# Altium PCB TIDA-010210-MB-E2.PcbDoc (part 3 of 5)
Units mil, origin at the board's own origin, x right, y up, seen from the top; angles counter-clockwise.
Board outline 11811.02 x 8661.42 mil, 4 copper layers (Top Layer, Gnd Layer, Pwr Layer, Bottom Layer), stack 94.4 mil thick; 473 components, 257 nets, 1291 pads, 289 vias.
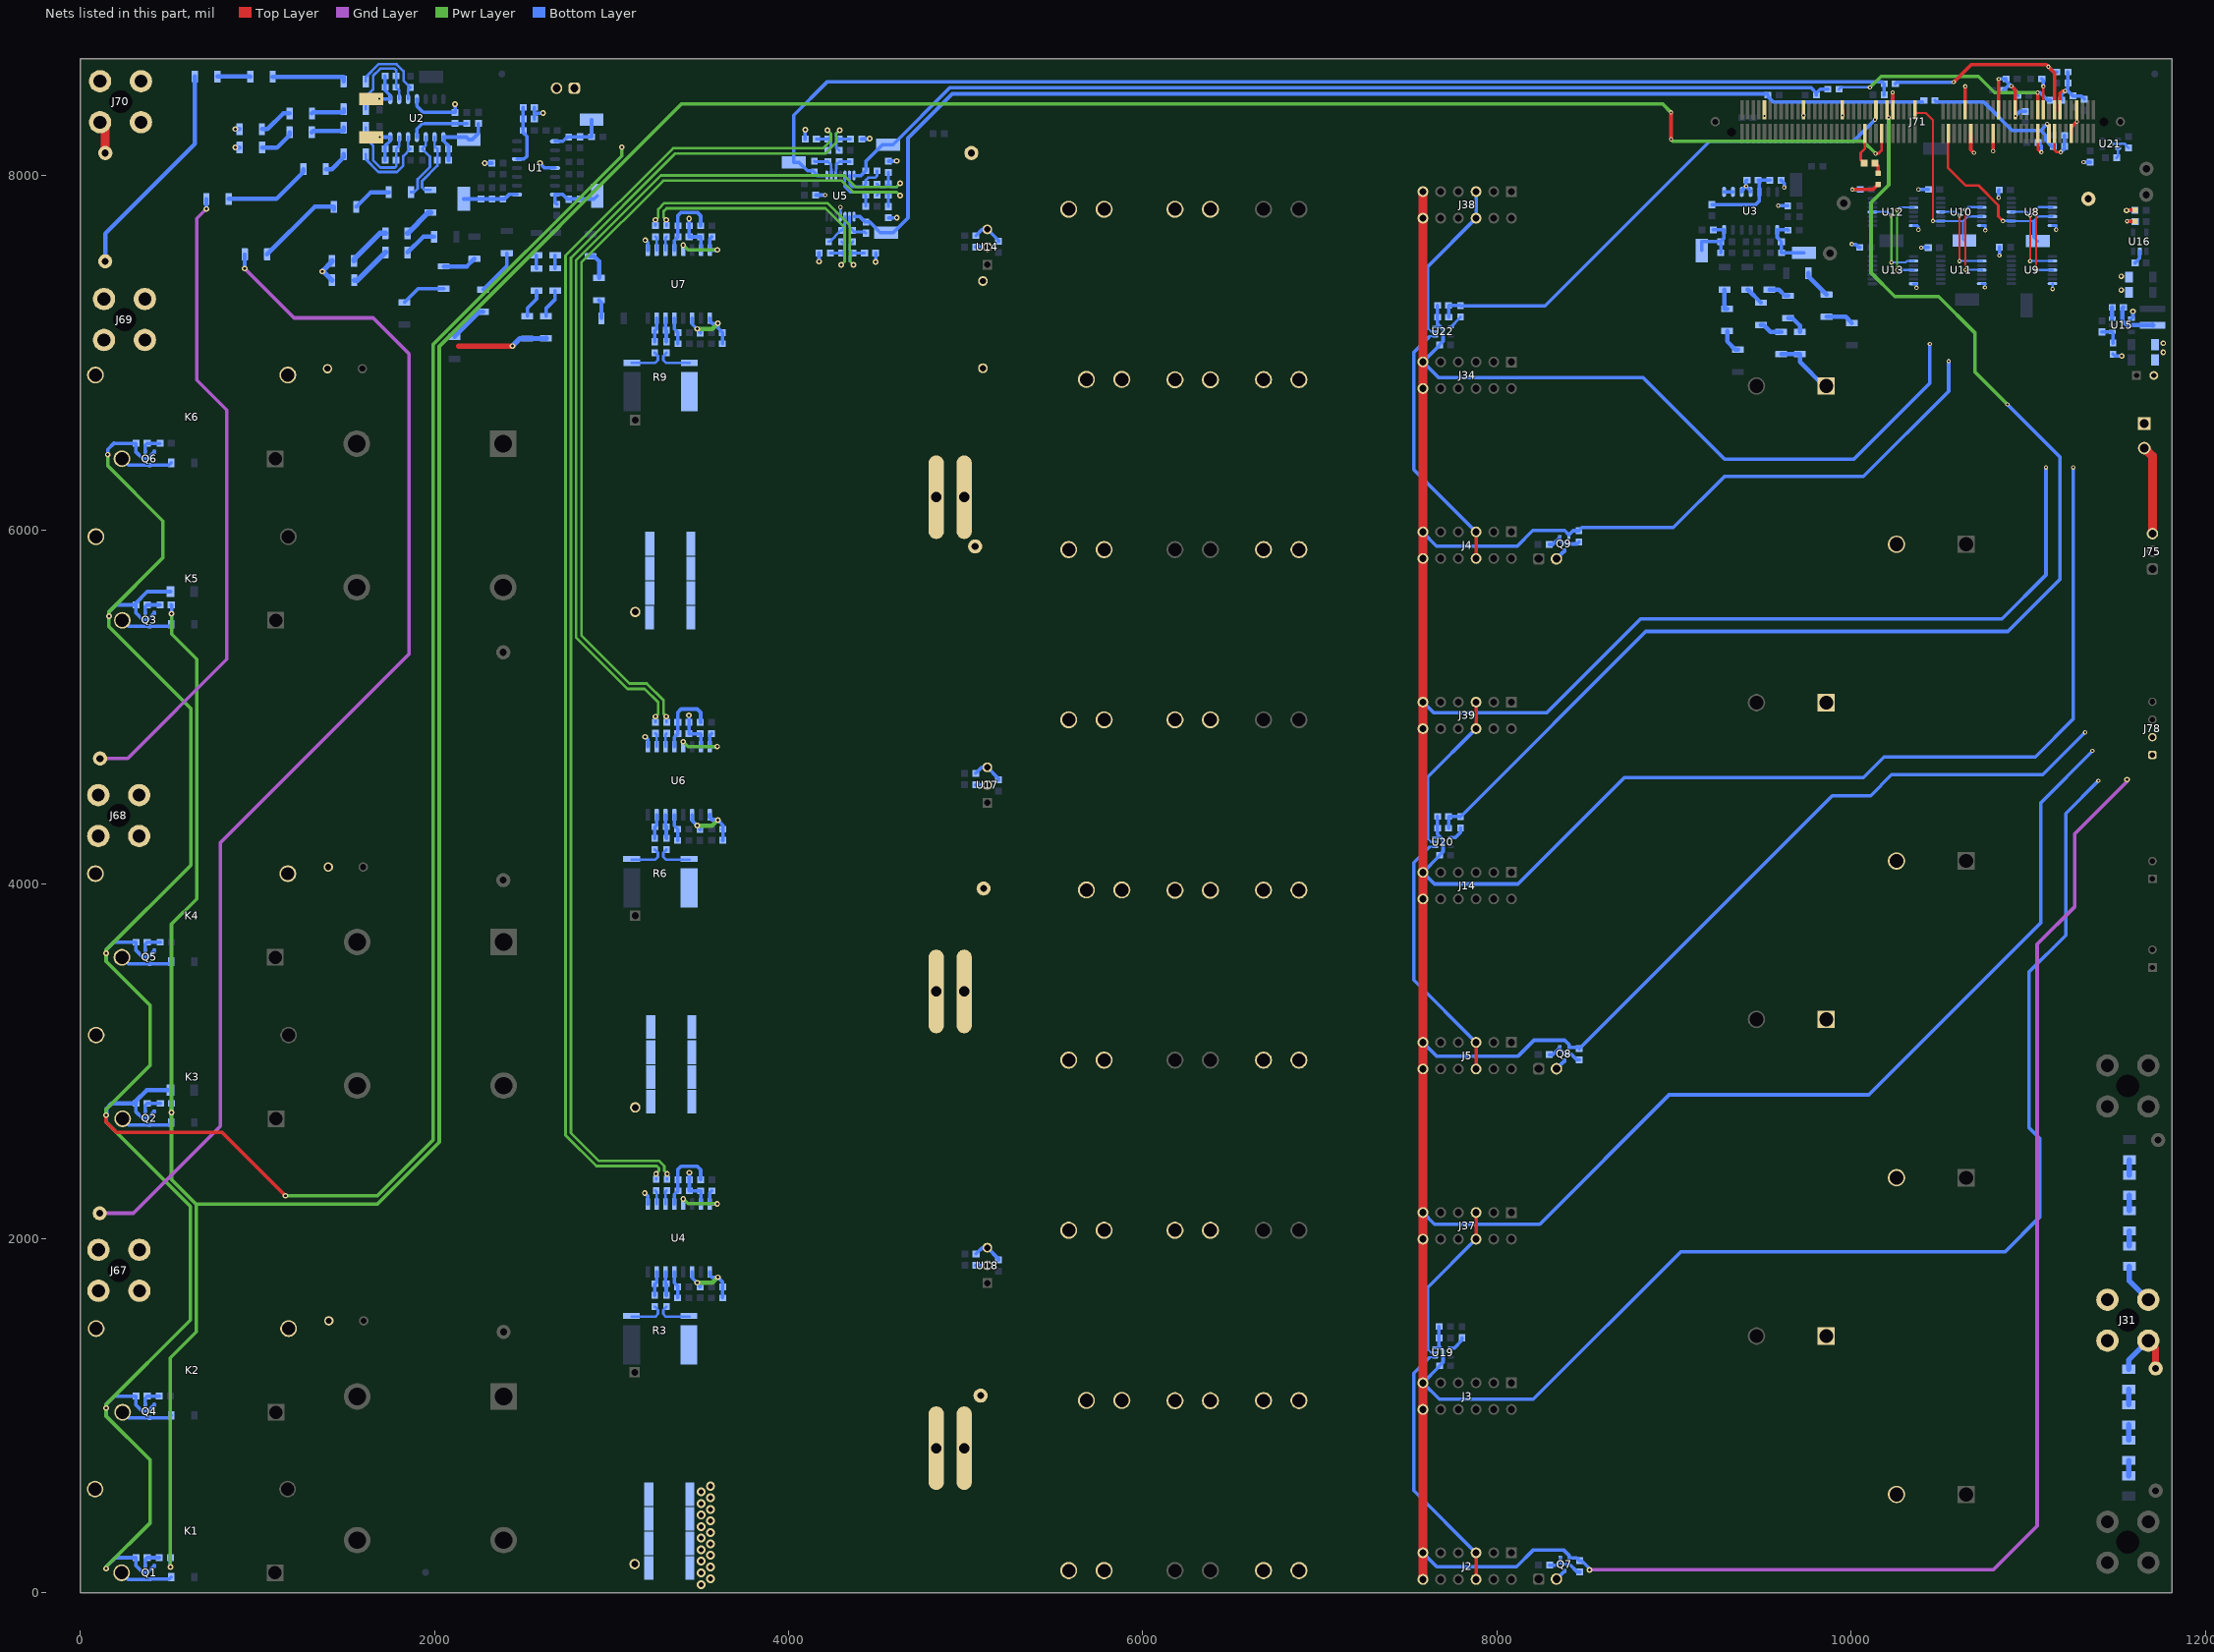
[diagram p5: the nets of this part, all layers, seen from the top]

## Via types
v1: diameter 24, hole 12, Top Layer to Bottom Layer, tented both sides, 169 vias
v2: diameter 32, hole 16, Top Layer to Bottom Layer, tented both sides, 102 vias
v3: diameter 50, hole 28, Top Layer to Bottom Layer, tented both sides, 18 vias

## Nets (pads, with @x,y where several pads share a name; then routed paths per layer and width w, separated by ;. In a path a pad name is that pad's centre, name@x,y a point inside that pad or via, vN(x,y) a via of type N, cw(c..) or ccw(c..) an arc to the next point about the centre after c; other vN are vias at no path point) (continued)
FAULT_A+: J2.3 U19.1 | length 1467.3
  Top Layer w20: J2.3@7881.32,75.11 J2.3@7881.32,225.11
  Bottom Layer w12: 7616.09,1325.31 7621.5,1330.72 U19.1@7649.8,1330.72
  Bottom Layer w20: 7616.09,1325.31 7530,1239.21 7530,576.43 J2.3@7881.32,225.11
FAULT_A-: J37.3 U19.2 | length 934.6
  Top Layer w20: J37.3@7881.32,1996.37 J37.3@7881.32,2146.37
  Bottom Layer w12: 7607.09,1377.09 7607.09,1376.31 7627.09,1356.31 U19.2@7649.8,1356.31
  Bottom Layer w20: 7607.09,1377.09 7607.09,1722.14 J37.3@7881.32,1996.37
FAULT_B: C99.1 J71.67 R152.2 R154.2 | length 7356.9
  Top Layer w15: J71.67@10202.02,8371.93 10202.02,8341.98 10210.7,8333.3 10210.7,8328 v1(10211,8328)
  Pwr Layer w20: v1(10211,8328) 10211,7948 10111,7848 10111,7452 10245,7318 10493,7318 10697,7114 10697,6893 v1(10881,6709)
  Bottom Layer w20: R154.2@7726.5,4316 C99.1@7726.5,4382 7791.5,4382 R152.2@7793,4380.5 8839.5,5427 10884,5427 11178,5721 11178,6412 v1(10881,6709)
FAULT_B+: J5.3 U20.1 | length 1467.3
  Top Layer w20: J5.3@7881.32,2957 J5.3@7881.32,3107
  Bottom Layer w12: 7616.09,4207.2 7621.5,4212.61 U20.1@7649.8,4212.61
  Bottom Layer w20: 7616.09,4207.2 7530,4121.1 7530,3458.32 J5.3@7881.32,3107
FAULT_B-: J39.3 U20.2 | length 934.6
  Top Layer w20: J39.3@7881.32,4878.26 J39.3@7881.32,5028.26
  Bottom Layer w12: 7607.09,4258.98 7607.09,4258.2 7627.09,4238.2 U20.2@7649.8,4238.2
  Bottom Layer w20: 7607.09,4258.98 7607.09,4604.03 J39.3@7881.32,4878.26
FAULT_C: C103.1 J71.71 R157.2 R159.2 | length 2966.6
  Top Layer w15: v1(10133,8316.47) 10139.03,8322.5 J71.71@10139.03,8371.93
  Bottom Layer w20: R159.2@7726.71,7201 7726.5,7201.21 C103.1@7726.5,7267 7791.41,7267 R157.2@7793,7265.41 8270.01,7265.41 9199.6,8195 10011.53,8195 v1(10133,8316.47)
FAULT_C+: J4.3 U22.1 | length 1467.3
  Top Layer w20: J4.3@7881.32,5838.89 J4.3@7881.32,5988.89
  Bottom Layer w12: 7616.09,7089.09 7621.5,7094.5 U22.1@7649.8,7094.5
  Bottom Layer w20: 7616.09,7089.09 7530,7002.99 7530,6340.21 J4.3@7881.32,5988.89
FAULT_C-: J38.3 U22.2 | length 934.6
  Bottom Layer w12: 7607.09,7140.87 7607.09,7140.09 7627.09,7120.09 U22.2@7649.8,7120.09
  Bottom Layer w20: 7607.09,7140.87 7607.09,7485.92 J38.3@7881.32,7760.15 J38.3@7881.32,7910.15
GND: C12.2 C13.1 C17.2 C18.2 C19.2 C23.2 C24.2 C25.2 C28.2 C29.2 C30.1 C31.2 C32.1 C33.1 C34.1 C37.1 C38.2 C39.2 C40.2 C42.2 C43.2 C45.1 C51.2 C52.2 C53.2 C55.2 C56.2 C58.1 C64.2 C65.2 C66.2 C68.2 C69.2 C71.1 C73.1 C74.2 C77.1 C78.1 C79.1 C80.1 C81.1 C82.1 C84.1 C85.1 C86.2 C87.2 C88.2 C89.2 C90.2 C91.2 C92.2 C93.1 C94.1 C95.2 C96.1 C97.1 C98.1 C99.2 C100.1 C101.1 C102.1 C103.2 C104.1 C105.2 D7.1 D8.1 J2.6 J3.6 J4.6 J5.6 J14.6 J34.6 J37.6 J38.6 J39.6 J71.7 J71.10 J71.13 J71.16 J71.19 J71.22 J71.29 J71.35 J71.38 J71.46 J71.47 J71.65 J71.83 J71.97 J71.111 J72.1 J72.2 J74.1 J78.1 J78.2 Q1.2 Q2.2 Q3.2 Q4.2 Q5.2 Q6.2 Q7.2 Q8.2 Q9.2 R27.1 R28.1 R29.1 R30.1 R31.1 R32.1 R111.2 R141.2 R145.1 R150.1 R151.1 R154.1 R155.1 R159.1 R160.1 TP15.1 TP37.1 U1.11 U2.11 U3.10 U3.11 U4.9 U4.15 U5.11 U6.9 U6.15 U7.9 U7.15 U8.7 U9.7 U10.7 U11.7 U12.7 U13.7 U14.3 U15.1 U16.2 U17.3 U18.3 U19.3 U20.3 U21.2 U22.3 | length 75522.4
  Top Layer w15: v1(9509,8338) 9509.1,8338.1 J71.111@9509.1,8371.93 ; J71.22@11052.41,8238.07 11052.41,8147.21 11067.16,8132.46 v1(11073,8132.46) ; J71.19@11083.91,8371.93 v1@11083.91,8503.91 ; J71.16@11146.9,8238.07 11146.9,8146.71 11161.15,8132.46 v1(11181.62,8132.46) ; v1@11272.88,8305.76 J71.7@11272.88,8371.93
  Top Layer w20: v2@147,2699 v2(147,2696) 147,2657 204,2600 800,2600 v2(1159,2241) ; v1(9729.58,8339.7) J71.97@9729.58,8371.93 ; v1(9950,8339.7) v1(9950,8339.7) J71.83@9950.05,8371.93 ; v1(10006,7921.78) 10121.82,7921.78 D8.1@10150.54,7950.5 ; J71.65@10233.51,8371.93 v1(10233.51,8470.51) ; J71.47@10642.96,8371.93 v1(10642.96,8504.36) ; J71.46@10674.46,8238.07 10674.46,8146.54 10692.2,8128.8 v1(10692.67,8128.8) ; J71.38@10800.44,8238.07 10800.44,8138.93 v1(10801,8138.37) ; J71.35@10831.94,8371.93 v1(10831.94,8545) ; v1(10903,8505.94) 10926.43,8482.52 J71.29@10926.43,8371.93 v1(10926.43,8338) ; v1@11083.91,8503.91 v1(11084,8504) ; J71.13@11178.4,8371.93 11178.4,8465.45 11190.94,8478 v1(11206.12,8478) ; J71.10@11241.39,8238.07 11241.39,8272.74 v1(11273.64,8305) v1@11272.88,8305.76 ; v1(11556,7742.56) 11555.86,7742.42 D7.1@11601,7742.42
  Top Layer w50: J2.6@7581.32,75.11 J2.6@7581.32,225.11 J3.6@7581.32,1034.74 J3.6@7581.32,1184.74 J37.6@7581.32,1996.37 J37.6@7581.32,2146.37 J5.6@7581.32,2957 J5.6@7581.32,3107 J14.6@7581.32,3916.63 J14.6@7581.32,4066.63 J39.6@7581.32,4878.26 J39.6@7581.32,5028.26 J4.6@7581.32,5838.89 J4.6@7581.32,5988.89 J34.6@7581.32,6798.52 J34.6@7581.32,6948.52 J38.6@7581.32,7760.15 J38.6@7581.32,7910.15
  Gnd Layer w20: v2(8521,129) 10801,129 11049,377 11049,3661 11262,3874 11262,4285.36 11557,4580.36 v2(11557,4591)
  Pwr Layer w20: v2(147,136) 147,146 396,395 396,748 147,997 v2(147,1043) 147,1063 623,1539 623,2181 147,2657 v2(147,2696) 147,2730 394,2977 394,3317 147,3564 v2(147,3610) 147,3629 625,4107 625,4992 163,5454 v2(163,5513) 163,5538 468,5843 468,6050 156,6362 v2(156,6425) ; v2(1159,2241) 1678.05,2241 1992.05,2555 1992.05,7045.58 3058,8111.53 v2(3058,8161)
  Bottom Layer w12: U19.3@7649.8,1381.9 7681.6,1381.9 ; U20.3@7649.8,4263.79 7681.6,4263.79 ; U22.3@7649.8,7145.68 7681.6,7145.68
  Bottom Layer w15: U5.11@4292.5,7768.77 v1(4292.5,7822.5) ; U13.7@10351.33,7389.93 10367.07,7389.93 10368,7389 v1(10368,7366.7) ; U12.7@10351.33,7718.01 10370.99,7718.01 10378.52,7710.48 v1(10378.52,7695) ; U11.7@10736.46,7390.33 10754.18,7390.33 v1(10754.18,7368.67) ; U10.7@10736.46,7718.41 10755.96,7718.41 v1(10755.96,7691.54) ; U9.7@11135.49,7390.33 11135.49,7360.61 v1@11135.93,7360.18 ; U8.7@11135.49,7718.41 11156.38,7718.41 v1(11156.38,7695) ; v1(11467,8174.5) 11472.85,8180.34 U21.2@11505.73,8180.34 11541.65,8180.34 C102.1@11564.73,8157.26
  Bottom Layer w20: v2(147,136) 147,146 199,198 R27.1@315.5,198 315.5,152.5 353.41,114.59 381.78,114.59 Q1.2@418.59,151.4 ; v2(147,1043) 147,1063 194,1110 R30.1@315.5,1110 315.5,1060.1 350.61,1025 382.19,1025 Q4.2@418.59,1061.4 ; v2(147,3610) 147,3629 191,3673 R31.1@315.5,3673 315.5,3626.31 353.81,3588 381.19,3588 Q5.2@418.59,3625.4 ; v2(156,6425) 156,6455 191,6490 192,6489 R32.1@315.5,6489 315.5,6439.5 353,6402 380.19,6402 Q6.2@418.59,6440.4 ; v2(163,5513) 163,5538 202,5577 R29.1@315.5,5577 ; R28.1@315.5,2763 315.5,2714.5 351,2679 381.19,2679 Q2.2@418.59,2716.4 ; Q3.2@418.59,5530.4 381.19,5493 353,5493 315.5,5530.5 R29.1@315.5,5577 ; C105.2@510.07,5652 379,5652 315.5,5588.5 R29.1@315.5,5577 ; U2.11@1900.98,8432.25 1900.98,8393.02 1936.53,8357.47 C33.1@2116.98,8357.47 v2(2116.98,8403.6) ; v2@2279.53,8070.53 C32.1@2324.34,8070.53 ; C73.1@2564.5,8320.39 2564.5,8352.69 ; R141.2@2564.5,8385 2564.5,8352.69 ; v2@2596,8070 2622.47,8043.53 U1.11@2681.12,8043.53 ; v2(2614,8353) 2613.69,8352.69 2564.5,8352.69 ; v2(3188,2257) 3204.94,2240.06 U4.9@3204.94,2194.86 ; v2(3190,4832) 3204.93,4817.07 U6.9@3204.93,4775.86 ; v2(3191,7636) 3205,7622 U7.9@3205,7579.86 ; v2(3437.35,4953.65) C53.2@3437.35,4913.74 C56.2@3437.35,4849.74 C58.1@3501.36,4849.74 3504.93,4846.17 U6.15@3504.93,4775.86 ; v2(3438.5,7756.56) C66.2@3438.5,7716.78 3438.42,7716.71 C69.2@3438.42,7654.61 C71.1@3503.5,7654.61 3505,7653.12 U7.15@3505,7579.86 ; v2(3439.43,2371.43) C40.2@3439.43,2331.78 C43.2@3439.43,2268.78 C45.1@3503.44,2268.78 3504.94,2267.29 U4.15@3504.94,2194.86 ; C42.2@4093.52,8206.91 v2@4093.52,8257.52 ; C37.1@4153,7890.5 4206.76,7890.5 v1(4207,7890.26) ; v2(4172.03,7515.03) C65.2@4172.03,7562.91 ; C39.2@4412.97,8206.91 v2@4455.91,8206.91 ; v2(4491.48,7513.52) C68.2@4491.48,7562.91 ; C52.2@4563.47,7762.26 v2(4611.13,7762.26) ; C55.2@4563.47,8081.71 v2@4610.71,8081.71 ; C94.1@5056.5,4626 5090.5,4660 U17.3@5121.95,4660 5185,4596.95 C93.1@5185,4588.5 ; C85.1@5057.55,7661.11 5093.43,7697 U14.3@5122,7697 5185.05,7633.95 C84.1@5185.05,7629.56 ; C98.1@5058.5,1913 5093.5,1948 U18.3@5121.95,1948 5185,1884.95 C97.1@5185,1879.31 ; J2.6@7581.32,225.11 7659.43,147 8110,147 8205,242 8375,242 8407.59,209.41 Q7.2@8407.59,197.4 8449.09,197.4 R151.1@8466,180.5 8478.93,180.5 v2@8521,138.42 ; J37.6@7581.32,2146.37 7646.69,2081 8241,2081 8971,2811 10098,2811 11070.5,3783.5 11070.5,4460.5 11361,4751 v1(11361,4753) ; J5.6@7581.32,3107 7658.32,3030 8119,3030 8208,3119 8382,3119 8405.59,3095.41 Q8.2@8405.59,3078.91 8456.59,3078.91 R155.1@8464,3071.5 9892.5,4500 10109,4500 10227,4618 11081,4618 v1(11320,4857) ; J39.6@7581.32,5028.26 7640.58,4969 8281,4969 8810,5498 10851,5498 11099,5746 v1(11099,6353) ; J4.6@7581.32,5986 7658.32,5909 8114,5909 8202,5997 8380.89,5997 8405.59,5972.3 8428.79,5995.5 R160.1@8462,5995.5 8479.5,6013 8995,6013 9284,6302 10068.4,6302 10549.4,6783 v1(10549.4,6953) ; C99.2@7663.5,4382 R154.1@7663.5,4316 7663.5,4281.88 7681.6,4263.79 7695.19,4250.19 7695.19,4183.82 7674.6,4163.23 7674.6,4159.91 J14.6@7581.32,4066.63 7646.95,4001 8117.9,4001 8718.9,4602 10068,4602 10185,4719 11039,4719 11253,4933 v1(11253,6353) ; C103.2@7663.5,7267 7663.5,7201.21 R159.1@7663.72,7201 7663.72,7163.56 7681.6,7145.68 7695.19,7132.08 7695.19,7065.71 7674.6,7045.12 7674.6,7041.8 J34.6@7581.32,6948.52 7669.84,6860 8824,6860 9285,6399 10014.03,6399 10443.27,6828.24 v1(10443.27,7049.5) ; R150.1@7672.5,1503.26 C95.2@7672.5,1438.26 7672.5,1390.99 7681.6,1381.9 7695.19,1368.3 7695.19,1301.93 C96.1@7674.6,1281.34 7674.6,1278.02 J3.6@7581.32,1184.74 7674.06,1092 8203.5,1092 9035.5,1924 10866.43,1924 11063,2120.57 11063,2566 11002,2627 11002,3503 11211,3712 11211,4400 v1(11395,4584) ; U3.10@9381.14,7908.56 9381.14,7915.14 v1(9406,7940) ; R111.2@9410.65,7975.27 9406,7970.63 v1(9406,7940) ; U3.11@9431.14,7908.56 9431.14,7914.86 v1(9406,7940) ; v1(9586.5,7830.5) C34.1@9641,7830.5 ; C30.1@9603.5,7974 9621,7956.5 v1(9621,7933) ; v1@10002,7612 10025,7612 10042.22,7594.78 C78.1@10047.69,7594.78 ; v1(10006,7921.78) C81.1@10049.69,7921.78 ; v1(10379.18,7922.18) C77.1@10435.32,7922.18 ; v1(10394.19,7593.96) 10394.41,7594.18 C80.1@10434.32,7594.18 ; v1(10831.96,7875.54) 10831.96,7917.45 C82.1@10834.5,7920 ; v1(10831.94,8545) 10832.94,8546 C29.2@10873.5,8546 10873.5,8535.44 v1(10903,8505.94) ; v1(10835.85,7549.2) C79.1@10835.85,7596.18 ; C17.2@10859.99,8482.84 10883.1,8505.94 v1(10903,8505.94) ; v1(10926.43,8338) 10951.31,8362.89 C28.2@10982,8362.89 ; C24.2@10939.67,8453 10939.67,8469.28 v1(10903,8505.94) ; C31.2@11053.99,8187 11073,8167.99 v1(11073,8132.46) ; C18.2@11075.1,8546 11084,8537.1 v1(11084,8504) ; v1(11181.62,8132.46) 11184.73,8132.46 11203.37,8151.1 C64.2@11203.37,8165.16 11203.37,8227.75 C23.2@11203.12,8228 ; C51.2@11186.97,8426 11186.97,8458.86 v1(11206.12,8478) ; C38.2@11223.05,8585 11223.05,8494.93 v1(11206.12,8478) ; v1(11310.65,8076) 11311.15,8076.5 C101.1@11348.68,8076.5 ; C19.2@11315.73,8431.99 11297.22,8450.5 C25.2@11250.84,8450.5 11223.33,8478 v1(11206.12,8478) ; R145.1@11478,6992.5 11488.51,6981.99 v2(11526.85,6981.99) ; v1(11556,7742.56) 11600.66,7742.56 C92.2@11602.51,7740.71 ; U15.1@11581.13,7193.32 11590,7202.18 v2(11590,7233.91) ; C91.2@11602.51,7507.71 11627.94,7533.14 11627.94,7572.73 U16.2@11628,7572.78
  Bottom Layer w25: v2(147,2696) 147,2731 179,2763 R28.1@315.5,2763 315.5,2776.5 377,2838 C12.2@510.07,2838
  other v1: 11136.08,7360.03 10002.19,7613.77
  other v2: 11761,7002.91 11761,7053.91 11524,7354 11524,7431.91 2284,8071 2596,8072 4610.49,8083 4458,8209 4095,8259
GVA_N: C15.2 R34.1 R41.2 U2.2 | length 380.3
  Bottom Layer w15: R41.2@1978,7918.99 1945.5,7918.99 1930.5,7934 1930.5,7969.5 2017.48,8056.48 R34.1@2017.48,8087.4 C15.2@2017.48,8150.89 2000.98,8167.4 U2.2@2000.98,8217.69
GVA_P: R53.2 R58.2 U2.3 | length 391
  Bottom Layer w15: R53.2@1867.99,7907 1885,7907 1905.5,7927.5 1905.5,7979.86 1975,8049.36 1975,8107.96 R58.2@1931.53,8151.44 1950.98,8170.89 U2.3@1950.98,8217.69
GVB_N: C21.2 R61.1 R68.2 U2.6 | length 523.2
  Bottom Layer w15: R68.2@1612.99,8271 1612.99,8211.01 1654,8170 1654,8087 1695,8046 1778,8046 1784.47,8052.47 R61.1@1784.47,8087.4 C21.2@1784.47,8150.96 1800.98,8167.46 U2.6@1800.98,8217.69
GVB_P: R80.2 R85.2 U2.5 | length 467.6
  Bottom Layer w15: R80.2@1612.99,8121 1612.99,8092.65 1684.64,8021 1788.36,8021 1824,8056.64 1824,8110.44 R85.2@1865,8151.44 1850.98,8165.46 U2.5@1850.98,8217.69
GVC_N: C27.2 R87.1 R94.2 U2.9 | length 526.1
  Bottom Layer w15: R94.2@1612.99,8375 1612.99,8444.99 1654,8486 1654,8563 1695,8604 1776,8604 1784.47,8595.53 R87.1@1784.47,8562.54 C27.2@1784.47,8498.98 1800.98,8482.48 U2.9@1800.98,8432.25
GVC_P: R102.2 R104.2 U2.10 | length 463.5
  Bottom Layer w15: R102.2@1612.99,8532 1612.99,8557.35 1684.64,8629 1786.36,8629 1826,8589.36 1826,8537.5 R104.2@1865,8498.5 1850.98,8484.48 U2.10@1850.98,8432.25
HB: J71.76 R161.1 | length 184.8
  Top Layer w15: R161.1@10071.5,8070.53 10053,8089.03 10053,8129.3 10076.03,8152.34 J71.76@10076.03,8238.07
IIND_A: R3.3 R119.1 | length 202.2
  Bottom Layer w15: R119.1@3310.48,1614.5 3292.48,1596.5 3292.48,1573.46 3307.57,1558.36 R3.3@3439.95,1558.36
IIND_A_RTN: R3.4 R115.1 | length 202
  Bottom Layer w15: R3.4@3115.14,1558.36 3247.3,1558.36 3262.48,1573.54 3262.48,1596.5 R115.1@3244.48,1614.5
Iind_B: R6.3 R128.1 | length 202.2
  Bottom Layer w15: R128.1@3310.47,4195.5 3292.47,4177.5 3292.47,4154.46 3307.57,4139.36 R6.3@3439.94,4139.36
Iind_B_Rtn: R6.4 R124.1 | length 202
  Bottom Layer w15: R6.4@3115.13,4139.36 3247.29,4139.36 3262.47,4154.54 3262.47,4177.5 R124.1@3244.47,4195.5
Iind_C: R9.3 R137.1 | length 202.2
  Bottom Layer w15: R137.1@3310.54,6999.5 3292.54,6981.5 3292.54,6958.46 3307.64,6943.36 R9.3@3440.01,6943.36
Iind_C_Rtn: R9.4 R133.1 | length 202
  Bottom Layer w15: R9.4@3115.2,6943.36 3247.36,6943.36 3262.54,6958.54 3262.54,6981.5 R133.1@3244.54,6999.5
INRSH_RY: J71.70 R21.1 R22.1 R23.1 | length 20799.9
  Top Layer w15: v1(10137,8125) 10152.23,8125 10170.52,8143.29 J71.70@10170.52,8238.07
  Top Layer w20: v1(8982,8205) v1(8982,8357)
  Pwr Layer w20: v2(509.5,145.5) 509.5,1325.5 509,1326 656,1472.99 656,2193 ; v2(516.5,5527) 516.5,5412.5 658,5271 658,3916.5 516,3774.5 v2(516,2712) 516,2333 656,2193 ; v1(8982,8205) 8992,8195 10067,8195 v1(10137,8125) ; v1(8982,8357) 8933,8406 3397.15,8406 2027.4,7036.26 2027.4,2543.88 1676.52,2193 656,2193
  Bottom Layer w20: v2(509.5,145.5) R21.1@509.5,198 ; R23.1@514.5,5577 516.5,5575 v2(516.5,5527) ; v2(516,2712) 516,2762.5 R22.1@516.5,2763
Isen_A: C38.1 J71.15 R116.2 | length 1230.6
  Top Layer w20: v1(10578,8528) 10677,8627 11101,8627 v1(11113,8615) 11146.9,8581.1 J71.15@11146.9,8371.93
  Bottom Layer w20: R116.2@10248.5,8519.47 10257.03,8528 v1(10578,8528) ; v1(11113,8615) 11143,8585 C38.1@11160.05,8585
Isen_A_N: C35.1 C42.1 R113.2 R114.1 | length 7682.2
  Pwr Layer w15: v2(3251.89,2365.11) 3267.88,2381.1 3267.88,2396.85 3256,2408.74 2914.62,2408.74 2741,2582.36 2741,7548.43 3347.57,8155 4195,8155 4238.47,8198.47 4238.42,8198.53 4238.42,8237.42 v2(4218.84,8257)
  Bottom Layer w15: R113.2@3251.89,2333.28 v2(3251.89,2365.11) ; C42.1@4156.51,8206.91 C35.1@4221.98,8206.91 ; v2(4218.84,8257) 4238.42,8237.42 4238.42,8223.35 C35.1@4221.98,8206.91 ; R114.1@4222.47,8142.41 4238.97,8158.91 4238.97,8189.92 C35.1@4221.98,8206.91
Isen_A_P: C35.2 C39.1 R117.2 R118.1 | length 7681.4
  Pwr Layer w15: 2770.95,2594.84 2927.05,2438.74 3268.43,2438.74 3297.88,2409.28 3297.88,2381.1 v2(3313.87,2365.11) ; 2771,2594.89 2771,7536 3360,8125 4207.43,8125 4268.47,8186.05 4268.42,8186.1 4268.42,8237.42 v2(4288,8257)
  Bottom Layer w15: R117.2@3313.87,2333.28 v2(3313.87,2365.11) ; 4268.42,8237.42 4268.47,8237.47 ; R118.1@4285.47,8142.41 4268.97,8158.91 4268.97,8190.92 C35.2@4284.97,8206.91 ; v2(4288,8257) 4268.47,8237.47 ; C39.1@4349.98,8206.91 C35.2@4284.97,8206.91 ; 4268.47,8237.47 4268.47,8223.41 C35.2@4284.97,8206.91
Isen_B: C51.1 J71.21 R125.2 | length 1378.1
  Top Layer w20: v1(11052,8469) 11052.41,8468.59 J71.21@11052.41,8371.93
  Pwr Layer w20: v1(10105,8497.61) 10168.39,8561 10717.47,8561 10809.47,8469 v1(11052,8469)
  Bottom Layer w15: R125.2@9930.5,8488.49 9941.38,8499.37 10103.23,8499.37 v1(10105,8497.61)
  Bottom Layer w20: v1(11052,8469) 11065.5,8469 11108.5,8426 C51.1@11123.98,8426
Isen_B_N: C49.1 C55.1 R122.2 R123.1 | length 5152.9
  Pwr Layer w15: v2(3247.86,4946.32) 3263.85,4962.32 3263.85,5026.15 3187,5103 3089.57,5103 2800.57,5392 2800,5392 2800,7522.43 3279.1,8001.53 4312.9,8001.53 4377.67,7936.76 4610.49,7936.76 v2(4630.07,7956.34)
  Bottom Layer w15: R122.2@3247.86,4914.5 v2(3247.86,4946.32) ; R123.1@4498.97,7952.76 4515.47,7936.26 4546.48,7936.26 C49.1@4563.47,7953.25 ; C55.1@4563.47,8018.72 C49.1@4563.47,7953.25 ; v2(4630.07,7956.34) 4610.49,7936.76 4579.97,7936.76 C49.1@4563.47,7953.25
Isen_B_P: C49.2 C52.1 R126.2 R127.1 | length 5102
  Pwr Layer w15: v2(3309.84,4946.32) 3293.85,4962.32 3293.85,5038.58 3199.43,5133 3102,5133 2830,5405 2830,7510 3291.53,7971.53 4300.47,7971.53 4365.24,7906.76 4610.49,7906.76 v2(4630.07,7887.18)
  Bottom Layer w15: R126.2@3309.84,4914.5 v2(3309.84,4946.32) ; R127.1@4498.97,7889.76 4515.47,7906.26 4547.48,7906.26 C49.2@4563.47,7890.26 ; C52.1@4563.47,7825.25 C49.2@4563.47,7890.26 ; v2(4630.07,7887.18) 4610.49,7906.76 4579.97,7906.76 C49.2@4563.47,7890.26
Isen_C: C64.1 J71.18 R134.2 | length 893.1
  Top Layer w20: J71.18@11108.37,8285.19 11115.4,8278.16 J71.18@11115.4,8238.07
  Bottom Layer w20: R134.2@10472.5,8425 10480.5,8417 10746,8417 10907,8256 11069.64,8256 ; v1(11105.64,8292) 11069.64,8256 ; C64.1@11140.38,8165.16 11132.05,8165.16 11097.71,8199.5 11097.71,8227.92 11069.64,8256
Isen_C_N: C62.1 C68.1 R131.2 R132.1 | length 1703.6
  Pwr Layer w15: v2(3247.93,7750.32) 3263.92,7766.32 3263.92,7810.43 3298.49,7845 4220.08,7845 4345.89,7719.19 4345.89,7545.26 4346.91,7544.23 4346.91,7515.51 v2(4366.11,7496.31)
  Bottom Layer w15: R131.2@3247.93,7718.5 v2(3247.93,7750.32) ; R132.1@4362.53,7627.42 4346.03,7610.92 4346.03,7579.91 C62.1@4363.02,7562.91 ; v2(4366.11,7496.31) 4346.53,7515.89 4346.53,7546.42 C62.1@4363.02,7562.91 ; C68.1@4428.49,7562.91 C62.1@4363.02,7562.91
Isen_C_P: C62.2 C65.1 R135.2 R136.1 | length 1603.6
  Pwr Layer w15: v2(3309.91,7750.32) 3293.92,7766.32 3293.92,7798 3310.92,7815 4207.65,7815 4315.89,7706.77 4315.89,7517.31 4316.91,7516.28 v2(4296.94,7496.31)
  Bottom Layer w15: R135.2@3309.91,7718.5 v2(3309.91,7750.32) ; C65.1@4235.02,7562.91 C62.2@4300.03,7562.91 ; v2(4296.94,7496.31) 4316.53,7515.89 4316.53,7546.42 C62.2@4300.03,7562.91 ; R136.1@4299.53,7627.42 4316.03,7610.92 4316.03,7578.91 C62.2@4300.03,7562.91
NetC9_2: C9.2 R18.2 R19.2 R20.2 R164.2
NetC10_2: C10.2 R12.2 R13.2 R14.2 R162.2
NetC11_2: C11.2 R15.2 R16.2 R17.2 R163.2
NetC14_1: C14.1 R33.2 R45.1 TP16.1 U1.1 | length 311.5
  Bottom Layer w20: TP16.1@2166,7869 2166.5,7868.5 R45.1@2263,7868.5 2263.47,7868.03 C14.1@2325.29,7868.03 R33.2@2387.29,7868.03 2396.2,7868.03 2421.7,7893.53 U1.1@2466.55,7893.53
NetC15_1: C15.1 R34.2 R46.1 TP18.1 U2.1 | length 416.3
  Bottom Layer w20: R34.2@2080.47,8087.4 2080.47,8167.42 2050.98,8196.92 U2.1@2050.98,8217.69 2180.31,8217.69 TP18.1@2194,8204 2213.26,8204 2249,8239.74 R46.1@2249,8295
NetC16_1: C16.1 R35.2 R47.1 TP17.1 U3.1 | length 329.1
  Bottom Layer w20: R47.1@9643.5,7692 9641.51,7693.99 U3.1@9581.14,7693.99 9581.14,7651.41 R35.2@9605.09,7627.47 9605.09,7565.15 C16.1@9605.61,7564.63 TP17.1@9731.97,7564.63
NetC20_1: C20.1 R60.2 R72.1 TP19.1 U1.14 | length 315.4
  Bottom Layer w20: R72.1@2691,7838.5 2681.12,7848.38 U1.14@2681.12,7893.53 2725.97,7893.53 2751.46,7868.03 C20.1@2822.38,7868.03 2900.03,7868.03 TP19.1@2919,7887
NetC21_1: C21.1 R61.2 R73.1 TP20.1 U2.7 | length 204.1
  Bottom Layer w20: R73.1@1690,8216.14 v1(1691.54,8217.69) U2.7@1750.98,8217.69 1750.98,8196.92 1721.48,8167.42 R61.2@1721.48,8087.4
NetC22_1: C22.1 R62.2 R74.1 TP21.1 U3.7 | length 356.3
  Bottom Layer w20: TP21.1@9156,7577.33 9156,7627.47 C22.1@9262.65,7627.47 ; R74.1@9219.14,7695.13 R74.1@9220.28,7693.99 U3.7@9281.14,7693.99 9281.14,7645.96 C22.1@9262.65,7627.47 ; R62.2@9262.65,7564.65 C22.1@9262.65,7627.47
NetC26_1: C26.1 R88.2 R95.1 TP22.1 U1.8 | length 314.3
  Bottom Layer w20: U1.8@2681.12,8193.53 2725.97,8193.53 2751.46,8219.02 C26.1@2822.38,8219.02 R95.1@2887.7,8219.02 2887.7,8315.7 TP22.1@2888,8316
NetC27_1: C27.1 R87.2 R96.1 TP23.1 U2.8 | length 204.4
  Bottom Layer w20: v1(1690,8434.5) 1692.24,8432.25 U2.8@1750.98,8432.25 1750.98,8453.02 1721.48,8482.52 C27.1@1721.48,8498.98 R87.2@1721.48,8562.54
NetC30_2: C30.2 R107.2 R111.1 U3.12 | length 464.7
  Bottom Layer w20: R107.2@9213,7836.5 9459.5,7836.5 9481.14,7858.14 U3.12@9481.14,7908.56 9481.14,7967.77 R111.1@9473.64,7975.27 9539.23,7975.27 C30.2@9540.5,7974
NetC33_2: C33.2 L8.2 U2.4 | length 340.9
  Bottom Layer w20: U2.4@1900.98,8217.69 1900.98,8263.98 1931.47,8294.47 C33.2@2116.98,8294.47 L8.2@2182.98,8294.47
NetC36_1: C36.1 R115.2 U4.7 | length 137.8
  Bottom Layer w20: R115.2@3244.48,1677.5 3244.48,1740.5 3245.98,1742 3254.94,1750.95 U4.7@3254.94,1811
NetC36_2: C36.2 R119.2 U4.6 | length 135.8
  Bottom Layer w20: U4.6@3304.94,1811 3304.94,1746.04 3308.98,1742 3308.98,1679 R119.2@3310.48,1677.5
NetC40_1: C40.1 C43.1 L11.1 U4.12 | length 404.2
  Bottom Layer w20: U4.12@3354.94,2194.86 3354.94,2249.18 3375.37,2269.61 3375.37,2331.71 3375.44,2331.78 3375.44,2390.5 3392.94,2408 3483.94,2408 3503.44,2388.5 L11.1@3503.44,2331.78
NetC41_2: C41.2 C44.1 C47.1 U4.1 U4.3 | length 430.1
  Pwr Layer w25: v2(3483.94,1750.05) 3569.46,1750.05 v2(3600.41,1781)
  Bottom Layer w20: U4.3@3454.94,1811 3454.94,1777.95 3500.87,1732.02 C47.1@3500.87,1727.5 ; U4.1@3554.94,1811 3554.94,1791.06 3565,1781 v2(3600.41,1781) 3627.43,1753.98 C41.2@3627.43,1726.46 ; C44.1@3626.43,1666 C41.2@3626.43,1729
NetC45_2: C45.2 U4.13 U4.16 | length 325.2
  Pwr Layer w20: v2(3404.94,2223) 3431.94,2196 v2(3596.94,2196)
  Bottom Layer w20: C45.2@3566.43,2269.61 3554.94,2258.12 U4.16@3554.94,2194.86 3595.8,2194.86 v2(3596.94,2196)
NetC46_2: C46.2 C48.1 U4.5 | length 154.3
  Bottom Layer w20: U4.5@3354.94,1811 3354.94,1749.5 3375.44,1729 C48.1@3375.44,1726.46 ; C48.1@3373.44,1726.46 3373.44,1668 C46.2@3375.44,1666
NetC50_1: C50.1 R124.2 U6.7 | length 137.8
  Bottom Layer w20: R124.2@3244.47,4258.5 3244.47,4321.5 3245.98,4323 3254.93,4331.95 U6.7@3254.93,4392
NetC50_2: C50.2 R128.2 U6.6 | length 135.8
  Bottom Layer w20: U6.6@3304.93,4392 3304.93,4327.04 3308.97,4323 3308.97,4260 R128.2@3310.47,4258.5
NetC53_1: C53.1 C56.1 L12.1 U6.12 | length 404.2
  Bottom Layer w20: U6.12@3354.93,4775.86 3354.93,4830.18 3375.36,4850.61 3375.36,4912.71 3375.43,4912.78 3375.43,4971.5 3392.93,4989 3483.93,4989 3503.43,4969.5 L12.1@3503.43,4912.78
NetC54_2: C54.2 C57.1 C60.1 U6.1 U6.3 | length 423.7
  Pwr Layer w25: v2(3483.93,4331.05) 3569.45,4331.05 v2(3600.4,4362)
  Bottom Layer w20: U6.3@3454.93,4392 3454.93,4358.95 3500.86,4313.02 C60.1@3500.86,4308.5 ; v2(3600.4,4362) 3629.05,4333.35 C54.2@3629.05,4311 ; C57.1@3626.43,4247 C57.1@3626.43,4248 ; C54.2@3627.24,4309.19 3629.05,4307.38 C57.1@3629.05,4248
  Bottom Layer w25: U6.1@3554.93,4392 3554.93,4378.07 3571,4362 v2(3600.4,4362)
NetC58_2: C58.2 U6.13 U6.16 | length 325.2
  Pwr Layer w20: v2(3404.93,4804) 3431.93,4777 v2(3596.93,4777)
  Bottom Layer w20: C58.2@3566.43,4850.61 3554.93,4839.12 U6.16@3554.93,4775.86 3595.79,4775.86 v2(3596.93,4777)
NetC59_2: C59.2 C61.1 U6.5 | length 152.9
  Bottom Layer w20: U6.5@3354.93,4392 3354.93,4330.5 C61.1@3374.43,4311 ; C61.1@3373.43,4310 3373.43,4249 C59.2@3375.43,4247
NetC63_1: C63.1 R133.2 U7.7 | length 137.8
  Bottom Layer w20: R133.2@3244.54,7062.5 3244.54,7125.5 C63.1@3246.05,7127 3255,7135.95 U7.7@3255,7196
NetC63_2: C63.2 R137.2 U7.6 | length 135.8
  Bottom Layer w20: U7.6@3305,7196 3305,7131.04 C63.2@3309.04,7127 3309.04,7064 R137.2@3310.54,7062.5
NetC66_1: C66.1 C69.1 L13.1 U7.12 | length 404.2
  Bottom Layer w20: U7.12@3355,7579.86 3355,7634.18 C69.1@3375.43,7654.61 3375.43,7716.71 C66.1@3375.5,7716.78 3375.5,7775.5 3393,7793 3484,7793 3503.5,7773.5 L13.1@3503.5,7716.78
NetC67_2: C67.2 C70.1 C75.1 U7.1 U7.3 | length 424.9
  Pwr Layer w25: v2(3484,7135.05) 3569.52,7135.05 v2(3600.47,7166)
  Bottom Layer w20: U7.3@3455,7196 3455,7162.95 3500.93,7117.02 C75.1@3500.93,7112.5 ; U7.1@3555,7196 3555,7180 3569,7166 v2(3600.47,7166) 3601.06,7165.41 3601.06,7139.43 C67.2@3626.5,7114 C70.1@3626.5,7051
NetC71_2: C71.2 U7.13 U7.16 | length 325.2
  Pwr Layer w20: v2(3405,7608) 3432,7581 v2(3597,7581)
  Bottom Layer w20: C71.2@3566.5,7654.61 3555,7643.12 U7.16@3555,7579.86 3595.86,7579.86 v2(3597,7581)
NetC72_2: C72.2 C76.1 U7.5 | length 153.5
  Bottom Layer w20: U7.5@3355,7196 3355,7134.5 C76.1@3375.5,7114 C72.2@3375.5,7051
NetC73_2: C73.2 R138.2 R141.1 U1.5 | length 332.5
  Bottom Layer w20: U1.5@2466.55,8093.53 2505.7,8093.53 2522,8109.83 2522,8222 R138.2@2501.52,8242.48 ; R138.2@2501.52,8255.85 C73.2@2501.5,8320.39 R141.1@2501.5,8385
NetC83_1: C83.1 L14.1 U15.2 | length 261.4
  Bottom Layer w25: C83.1@11535.5,7256.91 11528.82,7250.24 11528.82,7181.1 11554,7155.91 U15.2@11581.13,7155.91 L14.1@11700.5,7155.91
  Bottom Layer w30: L14.1@11700.5,7155.91 L14.1@11701,7155.41
NetC83_2: C83.2 U15.6 | length 63.7
  Bottom Layer w25: C83.2@11472.5,7256.91 11472.87,7256.55 U15.6@11472.87,7193.32
NetD1_2: D1.2 K1.2 Q1.3 | length 300.7
  Bottom Layer w20: K1.2@234.3,112.62 271.32,75.6 392,75.6 Q1.3@393,76.6 503.13,76.6 D1.2@514.53,88
NetD2_2: D2.2 K2.2 Q4.3 | length 294.1
  Bottom Layer w20: K2.2@239.86,1019 272.26,986.6 Q4.3@393,986.6 500.13,986.6 D2.2@514.53,1001
NetD3_2: D3.2 K3.2 Q2.3 | length 294.2
  Bottom Layer w20: K3.2@239.99,2675.56 273.95,2641.6 Q2.3@393,2641.6 501.13,2641.6 D3.2@514.53,2655
NetD4_2: D4.2 K4.2 Q5.3 | length 298.9
  Bottom Layer w20: K4.2@235.86,3587 272.26,3550.6 Q5.3@393,3550.6 502.13,3550.6 D4.2@514.53,3563
NetD5_2: D5.2 K5.2 Q3.3 | length 295.5
  Bottom Layer w20: K5.2@238.3,5489.62 272.32,5455.6 Q3.3@393,5455.6 502.13,5455.6 D5.2@514.53,5468
NetD6_2: D6.2 K6.2 Q6.3 | length 299.3
  Bottom Layer w20: K6.2@235.86,6402 272.26,6365.6 Q6.3@393,6365.6 501.13,6365.6 D6.2@514.53,6379
NetD7_2: D7.2 R143.2 | length 103
  Top Layer w20: v2@11548.31,7805.41 v2@11555.5,7805.41 ; v2(11553.78,7803.69) v2@11555.5,7805.41 ; D7.2@11601,7805.41 v2@11555.5,7805.41
  Bottom Layer w20: v2(11553.78,7803.69) 11554.28,7804.19 R143.2@11601.5,7804.19
NetD8_2: D8.2 R161.2 | length 63.7
  Top Layer w20: R161.2@10134.5,8070.53 10150.54,8054.48 D8.2@10150.54,8013.5
NetJ7_1: J7.1 J11.1 J60.1 J63.1
NetJ16_1: J16.1 J20.1 J24.1 J28.1
NetJ23_1: J23.1 J27.1 J35.1 J36.1
NetJ25_1: J25.1 J29.1 L2.1 TP3.1
NetJ26_1: J26.1 J30.1 J46.1 J50.1
NetJ32_1: J32.1 J33.1 J62.1 J65.1
NetJ40_1: J40.1 J41.1 L4.1 TP6.1
NetJ42_1: J42.1 J43.1 J61.1 J64.1
NetJ56_1: J56.1 J58.1 L6.1 TP8.1
NetJ74_2: J74.2 J75.3 | length 502.3
  Top Layer w50: J74.2@11654,6462.2 11700,6416.2 J75.3@11700,5979
NetJ79_2: J79.2 Q7.3 | length 65.9
  Bottom Layer w20: J79.2@8335,77 8336.4,77 Q7.3@8382,122.6
NetJ80_2: J80.2 Q8.3 | length 64.7
  Bottom Layer w20: J80.2@8335,2958 8380,3003 Q8.3@8380,3004.1
NetJ81_2: J81.2 Q9.3 | length 65.2
  Bottom Layer w20: J81.2@8335,5837 8380,5882 Q9.3@8380,5883.6
NetK1_3: K1.3 K2.4 RT1.1
NetK3_3: K3.3 K4.4 RT2.1
NetK5_3: K5.3 K6.4 RT3.1
NetL2_2: L2.2 R3.1
NetL4_2: L4.2 R6.1
NetL6_2: L6.2 R9.1
NetQ1_1: Q1.1 R21.2 R27.2 | length 119.2
  Bottom Layer w20: Q1.1@367.41,151.4 367.41,186.91 R27.2@378.5,198 R21.2@446.5,198
NetQ2_1: Q2.1 R22.2 R28.2 | length 126.2
  Bottom Layer w20: Q2.1@367.41,2716.4 367.41,2751.91 R28.2@378.5,2763 R22.2@453.5,2763
NetQ3_1: Q3.1 R23.2 R29.2 | length 124.2
  Bottom Layer w20: Q3.1@367.41,5530.4 367.41,5565.91 R29.2@378.5,5577 R23.2@451.5,5577
NetQ4_1: Q4.1 R24.2 R30.2 | length 122.2
  Bottom Layer w20: Q4.1@367.41,1061.4 367.41,1098.91 R30.2@378.5,1110 R24.2@447.5,1110
NetQ5_1: Q5.1 R25.2 R31.2 | length 126.2
  Bottom Layer w20: Q5.1@367.41,3625.4 367.41,3661.91 R31.2@378.5,3673 R25.2@452.5,3673
NetQ6_1: Q6.1 R26.2 R32.2 | length 126.2
  Bottom Layer w20: Q6.1@367.41,6440.4 367.41,6477.91 R32.2@378.5,6489 R26.2@451.5,6489
NetQ7_1: Q7.1 R149.2 R151.2 | length 223.1
  Bottom Layer w20: R149.2@8297,155.73 8336.55,155.73 8356.41,175.59 ; Q7.1@8356.41,197.4 8356.41,175.59 ; R151.2@8466,117.5 8452.5,117.5 8409,161 8371,161 8356.41,175.59
NetQ8_1: Q8.1 R153.2 R155.2 | length 220.6
  Bottom Layer w20: R153.2@8294.99,3038 8313.5,3038 Q8.1@8354.41,3078.91 8354.41,3069.59 8383,3041 8417.93,3041 8450.42,3008.5 R155.2@8464,3008.5
NetQ9_1: Q9.1 R158.2 R160.2 | length 213.8
  Bottom Layer w20: R158.2@8294.5,5918 8314.01,5918 Q9.1@8354.41,5958.4 8354.41,5942.59 8376,5921 8450.5,5921 R160.2@8462,5932.5
NetR1_1: R1.1 R2.2 | length 86.4
  Bottom Layer w30: R1.1@11566,660.32 R2.2@11566,746.71
NetR2_1: R2.1 R4.2 | length 86.4
  Bottom Layer w30: R2.1@11566,860.89 R4.2@11566,947.29
NetR4_1: R4.1 R5.2 | length 86.4
  Bottom Layer w30: R4.1@11566,1061.46 R5.2@11566,1147.86
NetR7_1: R7.1 R8.2 | length 86.4
  Bottom Layer w30: R7.1@11570,1956.6 R8.2@11570,2043
NetR8_1: R8.1 R10.2 | length 86.4
  Bottom Layer w30: R8.1@11570,2157.17 R10.2@11570,2243.57
NetR10_1: R10.1 R11.2 | length 86.4
  Bottom Layer w30: R10.1@11570,2357.74 R11.2@11570,2444.14
NetR36_2: R36.2 R37.1 | length 240.6
  Bottom Layer w30: R36.2@1547.46,7410 1566.01,7410 R37.1@1723.01,7567
NetR37_2: R37.2 R38.1 | length 186.5
  Bottom Layer w25: R37.2@1848.99,7567 1936.99,7655 R38.1@1999.01,7655
NetR39_2: R39.2 R40.1 | length 247.1
  Bottom Layer w30: R39.2@1546.99,7519 1546.99,7529.99 1692,7675 R40.1@1723.01,7675
NetR40_2: R40.2 R41.1 | length 177.9
  Bottom Layer w30: R40.2@1848.99,7675 1967,7793.01 R41.1@1978,7793.01
NetR42_2: R42.2 R43.1 | length 119.8
  Bottom Layer w25: R43.1@9643,7196.01 9666.99,7196.01 9710,7153 R42.2@9710,7117.99
NetR43_2: R43.2 R44.1 | length 120.5
  Bottom Layer w25: R44.1@9537,7357.01 9590.36,7357.01 9625.38,7321.99 R43.2@9643,7321.99
NetR48_2: R48.2 R49.1 | length 253.9
  Bottom Layer w20: R48.2@1831,7284.99 1908.02,7362.01 R49.1@2053,7362.01
NetR49_2: R49.2 R50.1 | length 190.8
  Bottom Layer w25: R49.2@2053,7487.99 2182.98,7487.99 R50.1@2226,7531.01
NetR51_2: R51.2 R52.1 | length 504
  Bottom Layer w25: R51.2@1055.99,7556.15 1323.84,7824 R52.1@1433.01,7824 R52.1@1433.01,7808.01
NetR52_2: R52.2 R53.1 | length 217.4
  Bottom Layer w25: R52.2@1558.99,7824 1641.99,7907 R53.1@1742.01,7907
NetR54_2: R54.2 R55.1 | length 157.4
  Bottom Layer w25: R55.1@9860,7203.02 9967.83,7203.02 R54.2@10002.86,7167.99
NetR55_2: R55.2 R56.1 | length 162.8
  Bottom Layer w25: R56.1@9757.99,7449.53 9757.99,7431.01 R55.2@9860,7329
NetR63_2: R63.2 R64.1 | length 165.3
  Bottom Layer w20: R63.2@2525.07,7206.22 2525.07,7252.07 2577,7304 R64.1@2577,7350.01
NetR64_2: R64.2 R65.1 | length 75.5
  Bottom Layer w20: R65.1@2575.76,7551.01 2575.76,7477.23 R64.2@2577,7475.99
NetR66_2: R66.2 R67.1 | length 200.1
  Bottom Layer w25: R66.2@1026.99,8158.73 1111.73,8158.73 1182.01,8229.01 R67.1@1182.01,8245
NetR67_2: R67.2 R68.1 | length 200.9
  Bottom Layer w25: R67.2@1307.99,8245 1314.99,8252 1487.01,8252 R68.1@1487.01,8271
NetR69_2: R69.2 R70.1 | length 139.1
  Bottom Layer w25: R70.1@9299,7123.01 9299,7064 9345.01,7017.99 R69.2@9360,7017.99
NetR70_2: R70.2 R71.1 | length 123
  Bottom Layer w25: R71.1@9284,7357.01 9284,7248.99 R70.2@9299,7248.99
NetR75_2: R75.2 R76.1 | length 219
  Bottom Layer w25: R75.2@2114,7090.98 2254.02,7231.01 R76.1@2275,7231.01
NetR76_2: R76.2 R77.1 | length 260.5
  Bottom Layer w20: R76.2@2275,7356.99 2409,7490.99 R77.1@2409,7562.01
NetR78_2: R78.2 R79.1 | length 501.4
  Bottom Layer w25: R78.2@838.59,7869 1109,7869 1261.01,8021.01 R79.1@1261.01,8037
NetR79_2: R79.2 R80.1 | length 145.9
  Bottom Layer w25: R79.2@1386.99,8037 1422,8037 1487.01,8102.01 R80.1@1487.01,8121
NetR81_2: R81.2 R82.1 | length 130.8
  Bottom Layer w25: R82.1@9489.76,7157.02 9504.98,7157.02 9544.01,7117.99 R81.2@9604.37,7117.99
NetR82_2: R82.2 R83.1 | length 107.8
  Bottom Layer w25: R83.1@9412.62,7357.01 9415.75,7357.01 R82.2@9489.76,7283
NetR89_2: R89.2 R90.1 | length 165.3
  Bottom Layer w20: R89.2@2630.07,7207.22 2630.07,7250.07 2682,7302 R90.1@2682,7351.01
NetR90_2: R90.2 R91.1 | length 74.3
  Bottom Layer w20: R90.2@2682,7476.99 R91.1@2682,7551.25
NetR92_2: R92.2 R93.1 | length 193.3
  Bottom Layer w25: R92.2@1026.24,8262.84 1057.85,8262.84 1146,8351 R93.1@1183.01,8351
NetR93_2: R93.2 R94.1 | length 197.3
  Bottom Layer w25: R93.2@1308.99,8351 1316.99,8359 1487.01,8359 R94.1@1487.01,8375
NetR97_2: R97.2 R98.1 | length 107.7
  Bottom Layer w20: R98.1@2929.24,7296.95 2943.01,7283.19 R97.2@2943.01,7195
NetR98_2: R98.2 R99.1 | length 152.4
  Bottom Layer w25: R99.1@2882,7544.01 2901.99,7544.01 2929.24,7516.76 R98.2@2929.24,7422.94
NetR100_2: R100.2 R101.1 | length 187
  Bottom Layer w25: R100.2@774.54,8559.39 959.62,8559.39 R101.1@961.01,8558
NetR101_2: R101.2 R102.1 | length 426
  Bottom Layer w25: R101.2@1086.99,8558 1487.01,8558 R102.1@1487.01,8532
NetR105_1: R105.1 R112.2 R116.1 TP26.1 U5.1 | length 6785.3
  Bottom Layer w20: U5.1@4214.59,8001.05 4163.84,8001.05 R112.2@4145.47,8019.42 4136.89,8028 4106,8028 4060,8074 TP26.1@4029,8074 4029,8342 4216,8529 10175.97,8529 R116.1@10185.5,8519.47 10185.21,8519.18 R105.1@10185.21,8456
NetR106_1: R106.1 R121.2 R125.1 TP27.1 U5.7 | length 5765.6
  Bottom Layer w20: U5.7@4370.41,8001.05 4409.4,8001.05 R121.2@4435.98,8027.63 4435.98,8080.98 4530,8175 TP27.1@4562,8175 4589,8175 4910,8496 9772.92,8496 R106.1@9802.5,8466.42 ; R106.1@9802.5,8455.57 R106.1@9802.5,8466.42 ; R125.1@9867.5,8488.49 9824.49,8488.49 9802.5,8466.5 R106.1@9802.5,8466.42
NetR109_1: R109.1 R130.2 R134.1 TP28.1 U5.8 | length 6679.7
  Bottom Layer w20: U5.8@4370.41,7768.77 4402.36,7768.77 4432.72,7738.41 R130.2@4436.47,7738.41 4458.59,7738.41 4518,7679 TP28.1@4551,7679 4591,7679 4674,7762 4674,8212 4924,8462 9523.08,8462 R109.1@9529.5,8455.57 9529.5,8445.5 9559,8416 R134.1@10400.01,8416
NetR112_1: R112.1 R114.2 U5.2 | length 164.4
  Bottom Layer w15: R112.1@4145.47,8082.41 4148.47,8079.42 R114.2@4222.47,8079.42 4239.11,8062.78 4239.11,8038.32 4241.32,8036.11 U5.2@4241.32,8001.05
NetR113_1: R113.1 U4.10 | length 78.6
  Bottom Layer w15: R113.1@3247.87,2270.5 3254.94,2263.43 U4.10@3254.94,2194.86
NetR117_1: R117.1 U4.11 | length 78.1
  Bottom Layer w15: U4.11@3304.94,2194.86 3304.94,2264.5 R117.1@3310.94,2270.5
NetR118_2: R118.2 R120.2 U5.3 | length 149.1
  Bottom Layer w15: U5.3@4266.91,8001.05 4266.91,8036.11 4269.11,8038.32 4269.11,8063.06 R118.2@4285.47,8079.42 R120.2@4348.47,8079.42
NetR121_1: R121.1 R123.2 U5.6 | length 276.3
  Bottom Layer w15: U5.6@4343.68,8001.05 4343.68,7965.99 4345.89,7963.79 4345.89,7950.63 4358.89,7937.63 4420.85,7937.63 R123.2@4435.98,7952.76 4435.98,7975.11 4449.5,7988.63 4487.5,7988.63 4498.97,8000.11 R121.1@4498.97,8027.63
NetR122_1: R122.1 U6.10 | length 78.6
  Bottom Layer w15: R122.1@3247.86,4851.5 3254.93,4844.43 U6.10@3254.93,4775.86
NetR126_1: R126.1 U6.11 | length 78.1
  Bottom Layer w15: U6.11@3304.93,4775.86 3304.93,4845.5 R126.1@3310.93,4851.5
NetR127_2: R127.2 R129.2 U5.5 | length 266.9
  Bottom Layer w15: U5.5@4318.09,8001.05 4318.09,7965.99 4315.89,7963.79 4315.89,7938.21 4346.46,7907.63 4418.26,7907.63 R127.2@4435.98,7889.91 R129.2@4435.98,7826.91
NetR130_1: R130.1 R132.2 U5.9 | length 166.3
  Bottom Layer w15: U5.9@4343.68,7768.77 4343.68,7733.71 4345.89,7731.51 4345.89,7707.05 R132.2@4362.53,7690.41 4370.3,7682.63 4429.26,7682.63 R130.1@4436.47,7675.42
NetR131_1: R131.1 U7.10 | length 78.6
  Bottom Layer w15: R131.1@3247.93,7655.5 3255,7648.43 U7.10@3255,7579.86
NetR135_1: R135.1 U7.11 | length 78.1
  Bottom Layer w15: U7.11@3305,7579.86 3305,7649.5 R135.1@3311,7655.5
NetR136_2: R136.2 R139.2 U5.10 | length 185.6
  Bottom Layer w15: R139.2@4226,7627.64 4232,7627.64 4294.77,7690.41 R136.2@4299.53,7690.41 4315.89,7706.77 4315.89,7731.51 4318.09,7733.71 U5.10@4318.09,7768.77
NetR142_1: R142.1 U14.2 | length 65
  Bottom Layer w20: R142.1@5057.04,7597.06 5057.1,7597 U14.2@5122,7597
NetR144_1: R144.1 R145.2 U15.4 | length 123.7
  Bottom Layer w20: R144.1@11414.52,7118.11 11414.93,7118.51 U15.4@11472.87,7118.51 11478,7113.38 R145.2@11478,7055.5
NetR146_1: R146.1 U17.2 | length 65
  Bottom Layer w20: R146.1@5056.99,4560.06 5057.05,4560 U17.2@5121.95,4560
NetR147_1: R147.1 U19.4 | length 96
  Bottom Layer w20: U19.4@7738.39,1381.9 7758.9,1381.9 7802,1425 R147.1@7802,1439.5
NetR148_1: R148.1 U18.2 | length 65
  Bottom Layer w20: R148.1@5056.99,1848.06 5057.05,1848 U18.2@5121.95,1848
NetR152_1: R152.1 U20.4 | length 91.4
  Bottom Layer w20: U20.4@7738.39,4263.79 7764.1,4263.79 7793,4292.68 R152.1@7793,4317.5
NetR156_1: R156.1 U21.3 | length 56.5
  Bottom Layer w15: R156.1@11497.23,8101.75 11505.73,8110.26 U21.3@11505.73,8154.75
NetR157_1: R157.1 U22.4 | length 79.4
  Bottom Layer w15: U22.4@7738.39,7145.68 7793,7200.29 R157.1@7793,7202.42
NetU3_8: U3.8 U3.9 | length 50
  Bottom Layer w20: U3.8@9281.14,7908.56 U3.9@9331.14,7908.56
NetU8_3: U8.3 U9.4 | length 533.2
  Top Layer w12: v1(11042.35,7468.18) v1(11042.35,7807.18)
  Bottom Layer w12: v1(11042.35,7807.18) 11057.22,7822.05 11135.49,7822.05 U8.3@11135.49,7820.77
  Bottom Layer w15: v1(11042.35,7468.18) 11043.43,7467.1 U9.4@11135.49,7467.1
NetU8_11: U8.11 U9.2 | length 500.8
  Top Layer w12: v1(11009.35,7518.18) v1(11009.35,7776.18)
  Bottom Layer w12: U8.11@10903.21,7795.18 10903.21,7797.05 10988.48,7797.05 v1(11009.35,7776.18) ; v1(11009.35,7518.18) 11009.45,7518.28 U9.2@11135.49,7518.28
NetU10_3: U10.3 U11.4 | length 532.7
  Top Layer w12: v1@10643.32,7467.18 v1@10643.32,7806.18
  Bottom Layer w12: v1(10643.32,7807.18) 10658.19,7822.05 10736.46,7822.05 U10.3@10736.46,7820.77 ; v1(10643.82,7468.18) 10735.38,7468.18 U11.4@10736.46,7467.1
NetU10_11: U10.11 U11.2 | length 500.8
  Top Layer w12: v1@10610.32,7517.18 v1@10610.32,7775.18
  Bottom Layer w12: U10.11@10504.18,7795.18 10504.18,7797.05 10589.45,7797.05 v1(10610.32,7776.18) ; v1(10610.32,7518.18) 10610.42,7518.28 U11.2@10736.46,7518.28
NetU12_3: U12.3 U13.4 | length 533.2
  Pwr Layer w12: v1(10258.19,7467.78) v1(10258.19,7806.78)
  Bottom Layer w12: v1(10258.19,7467.78) 10350.25,7467.78 U13.4@10351.33,7466.71 ; v1(10258.19,7806.78) 10273.06,7821.66 10351.33,7821.66 U12.3@10351.33,7820.37
NetU12_11: U12.11 U13.2 | length 511.7
  Pwr Layer w12: v1(10225.19,7775.78) 10226,7774.97 v1(10226,7509.76)
  Bottom Layer w12: U12.11@10119.04,7794.78 10119.04,7796.66 10204.31,7796.66 v1(10225.19,7775.78) ; v1(10226,7509.76) 10305,7509.76 10313.13,7517.89 U13.2@10351.33,7517.89
NEU: C1.2 C2.2 C3.2 C4.2 C5.1 C6.1 C7.1 C8.1 C13.2 J6.1 J8.1 J9.1 J10.1 J12.1 J13.1 J31.1 J52.1 J53.1 J54.1 J55.1 J57.1 J59.1 J70.1 R5.1 R7.2 R12.1 R13.1 R14.1 R15.1 R16.1 R17.1 R18.1 R19.1 R20.1 R36.1 R39.1 R42.1 R63.1 R66.1 R81.1 R89.1 R92.1 R162.1 R163.1 R164.1 TP5.1 TP13.1 | length 1868.6
  Top Layer w30: 2138,7038 v2(2441,7038)
  Top Layer w40: J31.1@11677,1422.95 11718,1381.95 TP5.1@11718,1266
  Top Layer w50: J70.1@112.4,8302 142,8272.4 TP13.1@142,8128
  Bottom Layer w25: v2(876.24,8263.11) 899.99,8263.11 R92.1@900.25,8262.84 ; v2(877,8159) 900.74,8159 R66.1@901.01,8158.73 ; R81.1@9604.37,6992.01 R42.1@9710,6992.01 9710,6948 9845,6813 C8.1@9857.96,6813
  Bottom Layer w30: R39.1@1421.01,7519 1421.01,7513.06 v2(1367,7459.06) 1372.43,7459.06 R36.1@1421.48,7410 ; v2(2441,7038) 2483.24,7080.24 R63.1@2525.07,7080.24 2629.07,7080.24 R89.1@2630.07,7081.24 ; R5.1@11566,1262.03 11566,1311.95 J31.1@11677,1422.95 ; R7.2@11570,1842.43 11570,1761.05 J31.1@11677,1654.05
  other v3: 3506,46.62 3559,78 3506,112.62 3558,144.78 3506,178 3558,211 3506,243 3558,275 3506,308 3558,340 3506,373 3558,405 3506,438 3558,471 3506,503 3558,536 3506,568.62 3558,601.62
PH_A: J67.1 K2.3 R51.1 TP10.1 | length 6894.5
  Gnd Layer w20: TP10.1@110.5,2142.38 300.38,2142.38 792,2634 792,4234 1857,5299 1857,6994 1654,7197 1207.98,7197 v2(929,7475.98)
  Bottom Layer w20: v2(929,7475.98) 929,7555.14 R51.1@930.01,7556.15
PH_B: J68.1 K4.3 R78.1 TP11.1 | length 3640.9
  Gnd Layer w20: TP11.1@112.56,4709.38 268.38,4709.38 828.59,5269.59 828.59,6676.41 659,6846 659,7759 712,7812 v2(713,7812)
  Bottom Layer w20: R78.1@712.61,7869 713,7868.61 v2(713,7812)
PH_C: J69.1 K6.3 R100.1 TP12.1 | length 1253
  Bottom Layer w25: TP12.1@141.56,7516.38 142,7516.82 142,7674 648.55,8180.55 R100.1@648.55,8559.39
PWM+_A: J71.54 TP32.1 U8.5 U8.9 | length 1079.9
  Top Layer w15: J71.54@10548.47,8238.07 10546,8235.6 10546,8044.19 10545.96,8044.15 10644.87,7945.24 10717.26,7945.24 10829.96,7832.54 10829.96,7770 v1(10855.96,7744)
  Bottom Layer w12: U8.9@10903.21,7744 11029.56,7744 11055.15,7769.59 U8.5@11135.49,7769.59
  Bottom Layer w15: v1(10855.96,7744) 10902.24,7744 U8.9@10903.21,7743.03 ; 11029.56,7744 11029.56,7652.92 TP32.1@11052.41,7630.06
PWM+_B: J71.57 TP33.1 U10.5 U10.9 | length 1099.2
  Top Layer w12: J71.57@10359.5,8371.93 10359.5,8364.5 10370,8354 10420.66,8354 10461,8313.66 v1(10461,7744)
  Bottom Layer w12: v1(10461,7744) 10503.21,7744 10504.18,7743.03 10630.68,7743.03 ; TP33.1@10638,7633.36 10630.68,7640.69 10630.68,7743.03 ; U10.5@10736.46,7769.59 10657.23,7769.59 10630.68,7743.03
